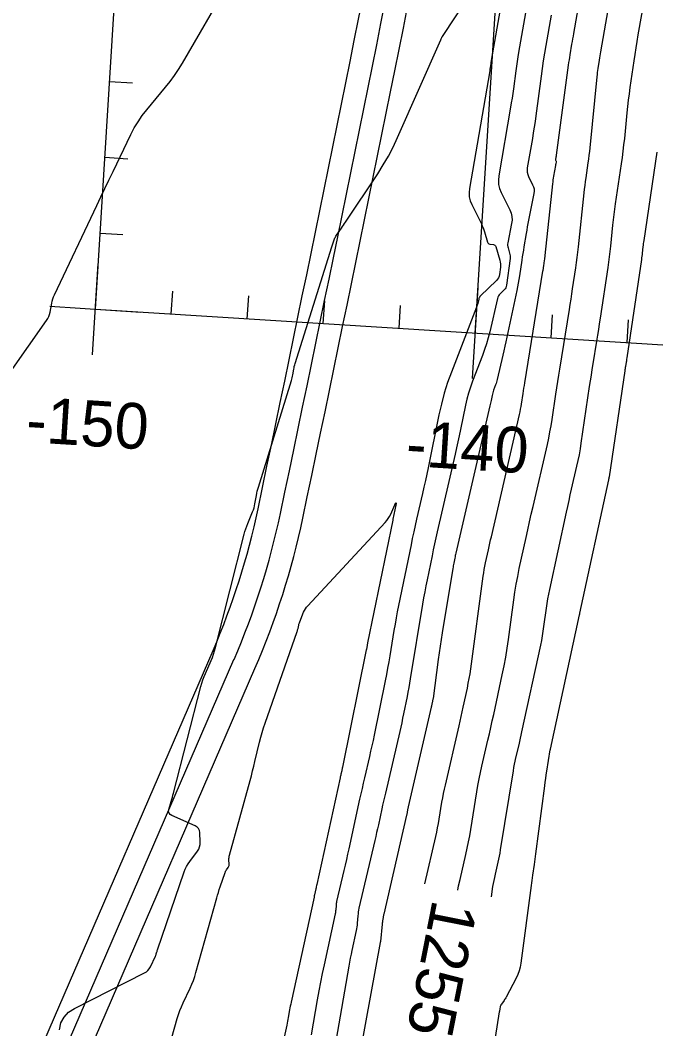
# Model space of a CAD drawing. Extents: x 658976 to 668726, y 639543 to 647196.
# Drawn here: x 661611.6 to 661695.1, y 641758.1 to 641890.7 of the extents above; entities that cross this region are included whole.
import ezdxf

# ---------------------------------------------------------------- set-up
doc = ezdxf.new("R2010")
doc.units = 0
for name, color, linetype in [('Ex_Contour Labels', 7, 'Continuous'), ('Ex_Major Contours', 7, 'Continuous'), ('Ex_Minor Contours', 7, 'Continuous'), ('R_Axis', 7, 'Continuous'), ('R_Axis Annot', 7, 'Continuous'), ('R_Grid', 7, 'Continuous'), ('R_Water', 7, 'Continuous')]:
    doc.layers.add(name, color=color, linetype=linetype)

msp = doc.modelspace()

# ---------------------------------------------------------------- linework, layer by layer
at = {"layer": 'Ex_Major Contours'}
for points in [[(661669.04, 641776.31), (661669.16, 641776.88), (661669.34, 641777.7), (661670.1, 641781), (661670.28, 641781.82), (661670.45, 641782.65), (661670.61, 641783.48), (661670.75, 641784.31), (661671.55, 641789.23), (661671.69, 641790.08), (661671.85, 641790.94), (661672.03, 641791.79), (661672.22, 641792.63), (661673, 641796.02), (661673.19, 641796.87), (661673.38, 641797.71), (661673.57, 641798.56), (661673.76, 641799.41), (661674.89, 641804.63), (661675.13, 641805.79), (661675.34, 641806.95), (661675.54, 641808.11), (661675.71, 641809.28), (661676.41, 641814.47), (661676.56, 641815.5), (661676.73, 641816.54), (661676.92, 641817.56), (661677.13, 641818.59), (661678.01, 641822.68), (661678.24, 641823.7), (661678.46, 641824.72), (661678.69, 641825.74), (661678.93, 641826.76), (661680.81, 641834.9), (661680.99, 641835.72), (661681.15, 641836.54), (661681.3, 641837.37), (661681.43, 641838.19), (661681.92, 641841.51), (661682.04, 641842.34), (661682.17, 641843.16), (661682.3, 641843.99), (661682.43, 641844.82), (661683.71, 641852.63), (661683.82, 641853.32), (661683.92, 641854), (661684.03, 641854.69), (661684.13, 641855.37), (661684.54, 641858.12), (661684.64, 641858.8), (661684.73, 641859.49), (661684.81, 641860.18), (661684.89, 641860.87), (661685.64, 641867.97), (661685.7, 641868.46), (661685.76, 641868.96), (661685.82, 641869.46), (661685.89, 641869.95), (661686.18, 641871.93), (661686.25, 641872.42), (661686.32, 641872.92), (661686.38, 641873.41), (661686.43, 641873.91), (661687.36, 641883.23), (661687.39, 641883.51), (661687.42, 641883.78), (661687.46, 641884.06), (661687.49, 641884.33), (661687.65, 641885.43), (661687.69, 641885.71), (661687.74, 641885.98), (661687.78, 641886.26), (661687.83, 641886.53), (661689.93, 641898.61)], [(661629.89, 641751.36), (661632.2, 641759.46), (661632.36, 641759.98), (661632.54, 641760.49), (661632.74, 641760.99), (661632.96, 641761.49), (661633.89, 641763.45), (661634.11, 641763.95), (661634.31, 641764.45), (661634.49, 641764.96), (661634.65, 641765.48), (661637.38, 641775.32), (661637.48, 641775.68), (661637.59, 641776.03), (661637.7, 641776.39), (661637.82, 641776.74), (661638.47, 641778.65), (661638.51, 641778.74), (661638.55, 641778.83), (661638.6, 641778.92), (661638.66, 641779), (661638.89, 641779.31), (661638.94, 641779.39), (661638.98, 641779.48), (661639, 641779.57), (661639, 641779.67), (661638.98, 641780.35), (661638.98, 641780.49), (661638.99, 641780.63), (661639.01, 641780.78), (661639.05, 641780.92), (661641.76, 641790.73), (661641.93, 641791.36), (661642.09, 641791.99), (661642.25, 641792.62), (661642.4, 641793.25), (661643, 641795.78), (661643.16, 641796.41), (661643.33, 641797.03), (661643.52, 641797.65), (661643.72, 641798.27), (661647.93, 641810.31), (661647.97, 641810.41), (661648, 641810.52), (661648.03, 641810.62), (661648.06, 641810.73), (661648.16, 641811.16), (661648.18, 641811.26), (661648.22, 641811.37), (661648.25, 641811.47), (661648.29, 641811.57), (661648.79, 641812.84), (661648.9, 641813.08), (661649.03, 641813.3), (661649.18, 641813.52), (661649.35, 641813.71), (661659.51, 641824.65), (661659.72, 641824.9), (661659.91, 641825.16), (661660.08, 641825.44), (661660.23, 641825.73), (661660.77, 641826.96), (661660.88, 641827.17), (661660.94, 641827.24), (661660.95, 641827.15), (661660.91, 641826.92), (661660.53, 641825.08), (661660.53, 641825.06), (661660.52, 641825.03), (661660.51, 641824.99), (661660.51, 641824.96), (661660.5, 641824.94), (661657.2, 641808.83), (661657.19, 641808.75), (661657.17, 641808.68), (661657.16, 641808.6), (661657.14, 641808.52), (661657.09, 641808.2), (661657.08, 641808.12), (661657.06, 641808.04), (661657.05, 641807.97), (661657.03, 641807.89), (661653.9, 641792.48), (661653.87, 641792.36), (661653.85, 641792.24), (661653.82, 641792.13), (661653.8, 641792.01), (661653.69, 641791.55), (661653.66, 641791.43), (661653.64, 641791.32), (661653.61, 641791.2), (661653.58, 641791.09), (661650.51, 641777.05), (661650.48, 641776.91), (661650.45, 641776.77), (661650.42, 641776.63), (661650.39, 641776.5), (661650.21, 641775.72), (661650.2, 641775.69), (661650.2, 641775.67), (661650.19, 641775.64), (661650.19, 641775.62), (661650.18, 641775.51), (661650.18, 641775.49), (661650.18, 641775.46), (661650.17, 641775.43), (661650.17, 641775.41), (661647.14, 641761.58), (661647.09, 641761.34), (661647.04, 641761.09), (661646.99, 641760.84), (661646.95, 641760.59), (661646.77, 641759.58), (661646.73, 641759.33), (661646.68, 641759.08), (661646.63, 641758.84), (661646.58, 641758.59), (661643.63, 641745.03)]]:
    msp.add_lwpolyline(points, dxfattribs=at)
at = {"layer": 'Ex_Minor Contours'}
for points in [[(661664.73, 641777.16), (661666.16, 641783.38), (661666.29, 641783.94), (661666.4, 641784.5), (661666.51, 641785.06), (661666.6, 641785.63), (661666.97, 641787.89), (661667.07, 641788.46), (661667.17, 641789.02), (661667.29, 641789.58), (661667.41, 641790.14), (661669.21, 641797.9), (661669.35, 641798.53), (661669.49, 641799.15), (661669.63, 641799.77), (661669.76, 641800.39), (661670.31, 641802.89), (661670.43, 641803.51), (661670.55, 641804.14), (661670.65, 641804.77), (661670.75, 641805.4), (661672.39, 641817.6), (661672.45, 641818.03), (661672.53, 641818.47), (661672.61, 641818.9), (661672.7, 641819.33), (661673.07, 641821.06), (661673.16, 641821.49), (661673.26, 641821.92), (661673.36, 641822.35), (661673.46, 641822.78), (661677.16, 641838.83), (661677.24, 641839.18), (661677.3, 641839.52), (661677.37, 641839.87), (661677.42, 641840.22), (661677.63, 641841.62), (661677.68, 641841.97), (661677.73, 641842.32), (661677.79, 641842.67), (661677.85, 641843.02), (661680.23, 641857.66), (661680.26, 641857.83), (661680.29, 641858.01), (661680.32, 641858.18), (661680.34, 641858.36), (661680.45, 641859.06), (661680.47, 641859.24), (661680.49, 641859.41), (661680.52, 641859.59), (661680.54, 641859.76), (661681.53, 641869.17), (661681.56, 641869.42), (661681.59, 641869.67), (661681.63, 641869.92), (661681.67, 641870.17), (661681.91, 641871.58), (661681.92, 641871.63), (661681.93, 641871.68), (661681.93, 641871.74), (661681.95, 641871.79), (661682, 641872.05), (661682, 641872.08), (661682, 641872.1), (661681.99, 641872.13), (661681.98, 641872.15), (661681.94, 641872.24), (661681.93, 641872.27), (661681.92, 641872.29), (661681.92, 641872.31), (661681.92, 641872.34), (661681.98, 641872.67), (661681.99, 641872.73), (661682, 641872.79), (661682.01, 641872.85), (661682.02, 641872.92), (661683.6, 641884.74), (661683.65, 641885.09), (661683.7, 641885.44), (661683.75, 641885.78), (661683.81, 641886.13), (661684.05, 641887.51), (661684.11, 641887.86), (661684.17, 641888.21), (661684.23, 641888.55), (661684.29, 641888.9), (661688.6, 641913.43)], [(661616.7, 641757.96), (661616.91, 641758.86), (661617.32, 641759.63), (661617.91, 641760.27), (661618.68, 641760.78), (661627.9, 641765.45), (661628.14, 641765.6), (661628.34, 641765.78), (661628.52, 641765.99), (661628.66, 641766.23), (661629.33, 641767.66), (661629.36, 641767.73), (661629.39, 641767.79), (661629.41, 641767.86), (661629.43, 641767.93), (661629.51, 641768.2), (661629.53, 641768.26), (661629.55, 641768.33), (661629.57, 641768.4), (661629.59, 641768.47), (661633.11, 641778.73), (661633.25, 641779.09), (661633.42, 641779.44), (661633.61, 641779.77), (661633.83, 641780.09), (661634.84, 641781.46), (661635.01, 641781.72), (661635.12, 641782), (661635.19, 641782.3), (661635.2, 641782.61), (661635.16, 641783.88), (661635.12, 641784.17), (661635, 641784.42), (661634.81, 641784.62), (661634.56, 641784.77), (661631.46, 641786.13), (661631.25, 641786.26), (661631.11, 641786.43), (661631.06, 641786.65), (661631.1, 641786.9), (661631.4, 641787.99), (661631.48, 641788.26), (661631.55, 641788.54), (661631.62, 641788.81), (661631.7, 641789.08), (661635.29, 641803.09), (661635.41, 641803.53), (661635.55, 641803.96), (661635.71, 641804.39), (661635.89, 641804.81), (661636.63, 641806.49), (661636.81, 641806.91), (661636.96, 641807.34), (661637.1, 641807.77), (661637.22, 641808.21), (661640.99, 641823.11), (661641.09, 641823.47), (661641.2, 641823.82), (661641.32, 641824.17), (661641.46, 641824.51), (661642.09, 641826.04), (661642.19, 641826.3), (661642.28, 641826.57), (661642.35, 641826.84), (661642.4, 641827.11), (661642.6, 641828.21), (661642.65, 641828.49), (661642.71, 641828.76), (661642.78, 641829.03), (661642.86, 641829.3), (661647.18, 641843.32), (661647.23, 641843.5), (661647.28, 641843.68), (661647.32, 641843.86), (661647.36, 641844.05), (661647.49, 641844.8), (661647.53, 641844.98), (661647.57, 641845.17), (661647.62, 641845.35), (661647.67, 641845.53), (661652.5, 641860.89), (661652.54, 641861.02), (661652.58, 641861.15), (661652.63, 641861.28), (661652.67, 641861.41), (661652.85, 641861.91), (661652.9, 641862.04), (661652.96, 641862.16), (661653.02, 641862.28), (661653.09, 641862.39), (661653.75, 641863.34), (661653.88, 641863.54), (661654.02, 641863.74), (661654.15, 641863.93), (661654.28, 641864.13), (661658.54, 641870.49), (661659.26, 641871.64), (661659.94, 641872.8), (661660.56, 641874), (661661.14, 641875.23), (661666.82, 641888.08), (661666.83, 641888.12), (661666.85, 641888.16), (661666.87, 641888.19), (661666.88, 641888.23), (661666.95, 641888.39), (661666.97, 641888.42), (661666.99, 641888.46), (661667.01, 641888.5), (661667.04, 641888.53), (661674.11, 641899.29)], [(661675.74, 641898.64), (661673.43, 641885.36), (661673.42, 641885.25), (661673.4, 641885.14), (661673.38, 641885.03), (661673.37, 641884.91), (661673.31, 641884.46), (661673.29, 641884.35), (661673.27, 641884.24), (661673.26, 641884.12), (661673.24, 641884.01), (661670.58, 641868.54), (661670.53, 641868), (661670.56, 641867.46), (661670.68, 641866.94), (661670.89, 641866.43), (661672.14, 641863.9), (661672.26, 641863.65), (661672.36, 641863.39), (661672.46, 641863.13), (661672.54, 641862.87), (661672.95, 641861.5), (661672.99, 641861.39), (661673.06, 641861.32), (661673.14, 641861.27), (661673.25, 641861.24), (661673.72, 641861.18), (661673.83, 641861.15), (661673.92, 641861.1), (661673.98, 641861.03), (661674.03, 641860.92), (661674.57, 641859.11), (661674.63, 641858.88), (661674.66, 641858.65), (661674.67, 641858.42), (661674.65, 641858.19), (661674.53, 641857.24), (661674.48, 641857.02), (661674.4, 641856.81), (661674.28, 641856.62), (661674.13, 641856.44), (661672.04, 641854.43), (661671.95, 641854.33), (661671.88, 641854.23), (661671.82, 641854.11), (661671.79, 641853.98), (661671.66, 641853.45), (661671.63, 641853.32), (661671.59, 641853.19), (661671.55, 641853.06), (661671.5, 641852.93), (661668.21, 641844.41), (661667.71, 641843.03), (661667.27, 641841.63), (661666.89, 641840.22), (661666.56, 641838.79), (661665.15, 641831.84), (661664.97, 641830.99), (661664.79, 641830.15), (661664.6, 641829.3), (661664.41, 641828.46), (661663.63, 641825.09), (661663.44, 641824.25), (661663.26, 641823.41), (661663.07, 641822.56), (661662.9, 641821.71), (661661.26, 641813.74), (661661.1, 641812.92), (661660.94, 641812.1), (661660.8, 641811.27), (661660.66, 641810.45), (661660.12, 641807.14), (661659.98, 641806.32), (661659.83, 641805.49), (661659.67, 641804.67), (661659.51, 641803.85), (661658.05, 641796.7), (661657.91, 641795.99), (661657.76, 641795.29), (661657.6, 641794.59), (661657.44, 641793.88), (661656.79, 641791.08), (661656.63, 641790.38), (661656.47, 641789.67), (661656.31, 641788.97), (661656.15, 641788.27), (661654.73, 641781.77), (661654.57, 641781.05), (661654.41, 641780.33), (661654.25, 641779.61), (661654.08, 641778.89), (661653.13, 641774.83), (661653.11, 641774.7), (661653.08, 641774.56), (661653.06, 641774.43), (661653.05, 641774.29), (661653.01, 641773.74), (661653, 641773.61), (661652.98, 641773.47), (661652.96, 641773.34), (661652.93, 641773.2), (661651.47, 641766.52), (661651.22, 641765.38), (661650.99, 641764.23), (661650.78, 641763.07), (661650.57, 641761.92), (661649.78, 641757.29)], [(661678.94, 641897.38), (661677.04, 641886.44), (661676.93, 641885.84), (661676.84, 641885.24), (661676.75, 641884.64), (661676.67, 641884.03), (661676.35, 641881.63), (661676.26, 641881.02), (661676.17, 641880.42), (661676.08, 641879.82), (661675.98, 641879.22), (661674.43, 641870.2), (661674.38, 641869.63), (661674.41, 641869.08), (661674.54, 641868.54), (661674.75, 641868.01), (661675.87, 641865.75), (661676.05, 641865.31), (661676.14, 641864.86), (661676.17, 641864.4), (661676.11, 641863.93), (661675.62, 641861.42), (661675.59, 641861.25), (661675.59, 641861.08), (661675.61, 641860.9), (661675.65, 641860.73), (661675.86, 641860.05), (661675.9, 641859.88), (661675.92, 641859.71), (661675.93, 641859.54), (661675.91, 641859.36), (661675.46, 641855.86), (661675.42, 641855.68), (661675.35, 641855.51), (661675.26, 641855.36), (661675.14, 641855.22), (661674.6, 641854.7), (661674.48, 641854.57), (661674.38, 641854.42), (661674.3, 641854.25), (661674.25, 641854.08), (661673.24, 641849.7), (661673.05, 641848.92), (661672.82, 641848.14), (661672.57, 641847.37), (661672.29, 641846.61), (661670.98, 641843.22), (661670.7, 641842.44), (661670.45, 641841.66), (661670.24, 641840.87), (661670.06, 641840.07), (661669.4, 641836.85), (661669.23, 641836.04), (661669.06, 641835.24), (661668.88, 641834.44), (661668.7, 641833.63), (661666.35, 641823.43), (661666.17, 641822.64), (661665.99, 641821.85), (661665.82, 641821.06), (661665.66, 641820.27), (661665.01, 641817.11), (661664.85, 641816.32), (661664.7, 641815.52), (661664.56, 641814.73), (661664.43, 641813.93), (661662.81, 641804.09), (661662.71, 641803.52), (661662.61, 641802.94), (661662.5, 641802.36), (661662.39, 641801.79), (661661.92, 641799.48), (661661.8, 641798.91), (661661.68, 641798.33), (661661.55, 641797.76), (661661.42, 641797.19), (661659.53, 641789.07), (661659.41, 641788.55), (661659.29, 641788.03), (661659.17, 641787.51), (661659.06, 641786.99), (661658.61, 641784.92), (661658.49, 641784.4), (661658.38, 641783.88), (661658.26, 641783.36), (661658.14, 641782.85), (661656.06, 641773.94), (661656.01, 641773.7), (661655.97, 641773.46), (661655.94, 641773.21), (661655.91, 641772.96), (661655.84, 641771.98), (661655.82, 641771.73), (661655.78, 641771.48), (661655.74, 641771.24), (661655.69, 641771), (661655.13, 641768.4), (661655.02, 641767.89), (661654.91, 641767.37), (661654.82, 641766.86), (661654.72, 641766.34), (661652.29, 641752.16)], [(661610.28, 641844.46), (661615.03, 641851.2), (661615.18, 641851.45), (661615.31, 641851.72), (661615.41, 641851.99), (661615.48, 641852.28), (661615.7, 641853.46), (661615.77, 641853.75), (661615.85, 641854.04), (661615.95, 641854.32), (661616.07, 641854.59), (661621.64, 641866.33), (661622.17, 641867.44), (661622.69, 641868.55), (661623.22, 641869.65), (661623.75, 641870.76), (661626.1, 641875.65), (661626.54, 641876.5), (661627.04, 641877.33), (661627.58, 641878.12), (661628.18, 641878.88), (661630.66, 641881.85), (661631.26, 641882.61), (661631.83, 641883.39), (661632.36, 641884.19), (661632.87, 641885.02), (661638.89, 641895.39)], [(661673.46, 641775.44), (661673.67, 641776.8), (661673.74, 641777.2), (661673.82, 641777.6), (661673.9, 641778), (661673.99, 641778.4), (661674.35, 641780), (661674.44, 641780.39), (661674.53, 641780.8), (661674.6, 641781.2), (661674.67, 641781.6), (661676.36, 641791.99), (661676.43, 641792.43), (661676.51, 641792.86), (661676.6, 641793.29), (661676.69, 641793.72), (661677.09, 641795.42), (661677.19, 641795.85), (661677.28, 641796.28), (661677.38, 641796.71), (661677.47, 641797.14), (661679.94, 641808.54), (661680.07, 641809.14), (661680.18, 641809.74), (661680.28, 641810.35), (661680.37, 641810.96), (661680.7, 641813.4), (661680.79, 641814), (661680.89, 641814.61), (661681, 641815.22), (661681.12, 641815.82), (661683.33, 641826.01), (661683.49, 641826.76), (661683.66, 641827.52), (661683.83, 641828.27), (661684, 641829.03), (661684.7, 641832.04), (661684.87, 641832.8), (661685.02, 641833.56), (661685.15, 641834.32), (661685.27, 641835.08), (661686.37, 641842.51), (661686.48, 641843.26), (661686.6, 641844.01), (661686.72, 641844.76), (661686.84, 641845.51), (661687.33, 641848.5), (661687.45, 641849.25), (661687.56, 641850), (661687.68, 641850.75), (661687.79, 641851.5), (661688.79, 641858.18), (661688.88, 641858.87), (661688.98, 641859.57), (661689.06, 641860.26), (661689.14, 641860.96), (661689.43, 641863.74), (661689.51, 641864.44), (661689.59, 641865.13), (661689.69, 641865.82), (661689.78, 641866.52), (661690.55, 641871.78), (661690.67, 641872.61), (661690.78, 641873.45), (661690.88, 641874.28), (661690.97, 641875.12), (661691.3, 641878.48), (661691.39, 641879.31), (661691.49, 641880.15), (661691.59, 641880.99), (661691.71, 641881.82), (661692.21, 641885.31), (661692.34, 641886.17), (661692.47, 641887.03), (661692.61, 641887.88), (661692.76, 641888.74), (661693.61, 641893.64)], [(661681.3, 641891.34), (661680.61, 641887.34), (661680.44, 641886.34), (661680.28, 641885.34), (661680.13, 641884.33), (661679.99, 641883.33), (661679.29, 641878.1), (661679.19, 641877.35), (661679.08, 641876.61), (661678.96, 641875.87), (661678.84, 641875.12), (661678.18, 641871.27), (661678.15, 641870.97), (661678.17, 641870.68), (661678.23, 641870.4), (661678.34, 641870.13), (661678.88, 641869.04), (661678.99, 641868.76), (661679.06, 641868.48), (661679.07, 641868.19), (661679.04, 641867.89), (661678.34, 641864.38), (661678.26, 641863.95), (661678.18, 641863.51), (661678.1, 641863.07), (661678.02, 641862.63), (661677.73, 641860.88), (661677.66, 641860.44), (661677.59, 641860), (661677.52, 641859.56), (661677.45, 641859.12), (661677.14, 641857.06), (661677.07, 641856.58), (661676.98, 641856.09), (661676.89, 641855.6), (661676.79, 641855.12), (661675.5, 641849), (661675.37, 641848.41), (661675.24, 641847.81), (661675.11, 641847.22), (661674.97, 641846.63), (661674.23, 641843.42), (661674.19, 641843.25), (661674.14, 641843.07), (661674.08, 641842.9), (661674.02, 641842.72), (661673.75, 641842.02), (661673.69, 641841.86), (661673.64, 641841.69), (661673.59, 641841.52), (661673.55, 641841.35), (661673.41, 641840.67), (661673.38, 641840.5), (661673.34, 641840.33), (661673.3, 641840.16), (661673.27, 641839.99), (661668.8, 641820.63), (661668.76, 641820.46), (661668.72, 641820.3), (661668.69, 641820.13), (661668.65, 641819.96), (661668.52, 641819.29), (661668.48, 641819.12), (661668.45, 641818.95), (661668.42, 641818.78), (661668.39, 641818.61), (661667, 641810.16), (661666.86, 641809.28), (661666.73, 641808.4), (661666.6, 641807.52), (661666.48, 641806.63), (661665.79, 641801.53), (661665.77, 641801.43), (661665.76, 641801.34), (661665.74, 641801.24), (661665.72, 641801.15), (661665.64, 641800.77), (661665.62, 641800.68), (661665.6, 641800.58), (661665.58, 641800.49), (661665.56, 641800.39), (661662.53, 641787.29), (661662.51, 641787.2), (661662.49, 641787.1), (661662.47, 641787.01), (661662.45, 641786.92), (661662.39, 641786.54), (661662.38, 641786.44), (661662.36, 641786.35), (661662.34, 641786.25), (661662.32, 641786.16), (661659.32, 641773.16), (661659.3, 641773.06), (661659.28, 641772.95), (661659.26, 641772.84), (661659.24, 641772.74), (661659.17, 641772.3), (661659.15, 641772.2), (661659.14, 641772.09), (661659.13, 641771.98), (661659.12, 641771.87), (661658.91, 641769.59), (661658.91, 641769.58), (661658.9, 641769.57), (661658.9, 641769.55), (661658.89, 641769.54), (661658.86, 641769.5), (661658.85, 641769.49), (661658.84, 641769.47), (661658.84, 641769.46), (661658.84, 641769.45), (661656.29, 641755.55)], [(661695.18, 641873.34), (661693.47, 641861.71), (661693.44, 641861.51), (661693.42, 641861.3), (661693.39, 641861.09), (661693.37, 641860.89), (661693.28, 641860.06), (661693.26, 641859.85), (661693.23, 641859.64), (661693.2, 641859.44), (661693.18, 641859.23), (661691.25, 641846.28), (661691.23, 641846.13), (661691.21, 641845.99), (661691.19, 641845.85), (661691.16, 641845.71), (661691.07, 641845.14), (661691.05, 641845), (661691.02, 641844.86), (661691, 641844.72), (661690.98, 641844.58), (661688.92, 641830.63), (661688.92, 641830.6), (661688.91, 641830.57), (661688.91, 641830.54), (661688.9, 641830.5), (661688.87, 641830.38), (661688.86, 641830.35), (661688.86, 641830.32), (661688.85, 641830.29), (661688.84, 641830.26), (661685.05, 641812.72), (661685.04, 641812.71), (661685.04, 641812.69), (661685.04, 641812.67), (661685.03, 641812.65), (661685.02, 641812.58), (661685.02, 641812.56), (661685.02, 641812.54), (661685.01, 641812.52), (661685.01, 641812.5), (661681.18, 641794.86), (661681.18, 641794.84), (661681.17, 641794.8), (661681.17, 641794.79), (661681.17, 641794.78), (661681.16, 641794.77), (661681.16, 641794.76), (661680.71, 641791.94), (661680.63, 641791.47), (661680.56, 641791), (661680.49, 641790.52), (661680.43, 641790.05), (661679.25, 641781.11), (661679.2, 641780.76), (661679.16, 641780.41), (661679.11, 641780.06), (661679.06, 641779.71), (661678.86, 641778.31), (661678.81, 641777.96), (661678.77, 641777.61), (661678.72, 641777.26), (661678.67, 641776.91), (661677.31, 641766.71), (661677.22, 641766.21), (661677.09, 641765.72), (661676.92, 641765.24), (661676.7, 641764.77), (661675.4, 641762.26), (661675.34, 641762.15), (661675.27, 641762.03), (661675.2, 641761.93), (661675.13, 641761.82), (661674.77, 641761.34), (661674.72, 641761.26), (661674.68, 641761.18), (661674.65, 641761.1), (661674.63, 641761.02), (661674.56, 641760.66), (661674.55, 641760.57), (661674.53, 641760.48), (661674.52, 641760.39), (661674.5, 641760.31), (661673, 641750.76)]]:
    msp.add_lwpolyline(points, dxfattribs=at)
at = {"layer": 'R_Axis'}
for p, q in [((661621.43, 641852.69), (661637.1, 642102.2)), ((661623.31, 641882.63), (661626.3, 641882.44)), ((661622.68, 641872.65), (661625.68, 641872.46)), ((661622.06, 641862.67), (661625.05, 641862.48)), ((661621.05, 641846.7), (661621.81, 641858.68)), ((661670.96, 641843.57), (661671.71, 641855.54)), ((661631.41, 641852.06), (661631.6, 641855.06)), ((661641.39, 641851.43), (661641.58, 641854.43)), ((661615.44, 641853.06), (661627.42, 641852.31)), ((661621.43, 641852.69), (663118.48, 641758.67)), ((661651.37, 641850.81), (661651.56, 641853.8)), ((661661.35, 641850.18), (661661.54, 641853.18)), ((661681.31, 641848.93), (661681.5, 641851.92)), ((661691.29, 641848.3), (661691.48, 641851.3))]:
    msp.add_line(p, q, dxfattribs=at)
at = {"layer": 'R_Grid'}
for p, q in [((661621.43, 641852.69), (661637.1, 642102.2)), ((661671.33, 641849.55), (661687, 642099.06)), ((661621.43, 641852.69), (663118.48, 641758.67))]:
    msp.add_line(p, q, dxfattribs=at)
at = {"layer": 'R_Water'}
for p, q in [((661540.52, 641585.06), (661636.89, 641807.82)), ((661536.1, 641567.27), (661639.64, 641806.63)), ((661556.63, 641607.19), (661642.4, 641805.44))]:
    msp.add_line(p, q, dxfattribs=at)
for centre, radius, start, end in [((654227.01, 643380.77), 7576.94, 348.162318, 349.545226), ((654227.01, 643380.77), 7579.94, 348.162318, 349.545226), ((654227.01, 643380.77), 7582.94, 348.162318, 349.545226), ((661547.87, 641846.34), 97, 336.6062, 348.1623), ((661547.87, 641846.34), 100, 336.6062, 348.1623), ((661547.87, 641846.34), 103, 336.6062, 348.1623)]:
    msp.add_arc(centre, radius, start, end, dxfattribs=at)

# ---------------------------------------------------------------- texts
at = {"layer": 'Ex_Contour Labels'}
msp.add_text('1255', height=6, rotation=258.8215, dxfattribs=at).set_placement((661665.78, 641775.26))
at = {"layer": 'R_Axis Annot'}
for s, p in [('-150', (661612.22, 641835.23)), ('-140', (661662.12, 641832.1))]:
    msp.add_text(s, height=6, rotation=356.4063, dxfattribs=at).set_placement(p)

doc.saveas('drawing.dxf')
